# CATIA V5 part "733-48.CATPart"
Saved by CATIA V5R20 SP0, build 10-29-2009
Part number: 733-48
Bounding box of the stored display mesh (mm): x -40 to 40, y -40 to 40, z -47 to 80
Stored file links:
  C:\Users\Utente\Desktop\IO LAVORO\3D X SITO CF\X SITO\733\733-48.CATPart
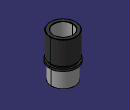
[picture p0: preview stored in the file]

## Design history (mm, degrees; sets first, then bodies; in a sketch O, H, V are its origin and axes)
Set1
  DatumSurface1 to DatumSurface25 "733-48"
Body1 (main body)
